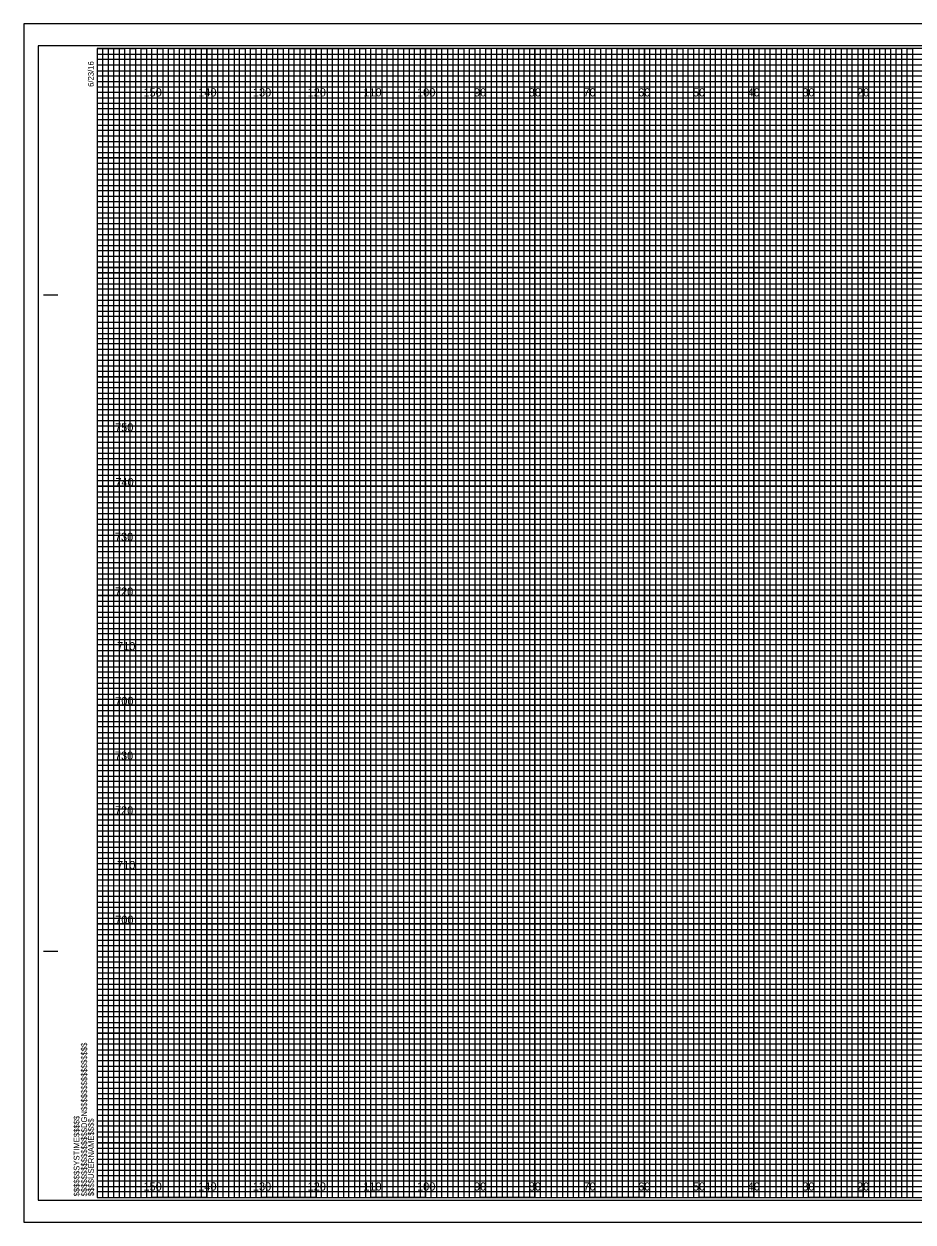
# Model space of a CAD drawing. Extents: x -397 to 323, y -4 to 654.
# Drawn here: x -13.4 to 149.1, y -4.5 to 214.5 of the extents above; entities that cross this region are included whole.
import ezdxf

# ---------------------------------------------------------------- set-up
doc = ezdxf.new("R2010")
doc.units = 0
for name, color, linetype in [('Default', 7, 'Continuous'), ('Prop XS Elevation Labels', 7, 'Continuous'), ('Prop XS Offset Labels', 7, 'Continuous'), ('Sheet Cross Section CELL', 7, 'Continuous'), ('Sheet Cross Section Grid Major CELL', 7, 'Continuous'), ('Sheet Cross Section Grid Middle CELL', 7, 'Continuous'), ('Sheet Cross Section Grid Minor 1 CELL', 7, 'Continuous'), ('Sheet Cross Section Grid Minor 2 CELL', 7, 'Continuous'), ('Sheet Cutting Line CELL', 7, 'Continuous'), ('Sheet DOT Grid CELL', 7, 'Continuous'), ('Sheet Plot Border Inside CELL', 7, 'Continuous'), ('Sheet Plot Border Outside CELL', 7, 'Continuous')]:
    doc.layers.add(name, color=color, linetype=linetype)

msp = doc.modelspace()

# ---------------------------------------------------------------- linework, layer by layer
at = {"layer": 'Default'}
msp.add_lwpolyline([(-13.4, -4.5), (323.3, -4.5), (323.3, 214.5), (-13.4, 214.5)], close=True, dxfattribs=at)
at = {"layer": 'Sheet Cross Section CELL'}
for p, q in [((-9.8, 165), (-7.3, 165)), ((-9.7, 165), (-7.2, 165)), ((-9.8, 45), (-7.3, 45)), ((-9.7, 45), (-7.2, 45)), ((0, 0), (0, 0)), ((0, 0), (0, 0)), ((0, 0), (0, 0)), ((0, 0), (0, 0)), ((0, 0), (0, 0)), ((0, 0), (0, 0)), ((0, 0), (0, 0))]:
    msp.add_line(p, q, dxfattribs=at)
msp.add_lwpolyline([(320, 210), (0, 210), (0, 0), (320, 0)], close=True, dxfattribs=at)
at = {"layer": 'Sheet Cross Section Grid Major CELL'}
for p, q in [((10, 210), (0, 210)), ((10, 0), (10, 210)), ((30, 210), (20, 210)), ((20, 210), (20, 0)), ((30, 0), (30, 210)), ((50, 210), (40, 210)), ((40, 210), (40, 0)), ((50, 0), (50, 210)), ((70, 210), (60, 210)), ((60, 210), (60, 0)), ((70, 0), (70, 210)), ((90, 210), (80, 210)), ((80, 210), (80, 0)), ((90, 0), (90, 210)), ((110, 210), (100, 210)), ((100, 210), (100, 0)), ((110, 0), (110, 210)), ((130, 210), (120, 210)), ((120, 210), (120, 0)), ((130, 0), (130, 210)), ((150, 210), (140, 210)), ((140, 210), (140, 0)), ((20, 0), (10, 0)), ((40, 0), (30, 0)), ((60, 0), (50, 0)), ((80, 0), (70, 0)), ((100, 0), (90, 0)), ((120, 0), (110, 0)), ((140, 0), (130, 0))]:
    msp.add_line(p, q, dxfattribs=at)
for points in [[(0, 200), (320, 200), (320, 190), (0, 190)], [(0, 180), (320, 180), (320, 170), (0, 170)], [(0, 160), (320, 160), (320, 150), (0, 150)], [(0, 140), (320, 140), (320, 130), (0, 130)], [(0, 120), (320, 120), (320, 110), (0, 110)], [(0, 100), (320, 100), (320, 90), (0, 90)], [(0, 80), (320, 80), (320, 70), (0, 70)], [(0, 60), (320, 60), (320, 50), (0, 50)], [(0, 40), (320, 40), (320, 30), (0, 30)], [(0, 20), (320, 20), (320, 10), (0, 10)]]:
    msp.add_lwpolyline(points, dxfattribs=at)
at = {"layer": 'Sheet Cross Section Grid Middle CELL'}
for points in [[(0, 210), (5, 210), (5, 0), (15, 0), (15, 210), (25, 210), (25, 0), (35, 0), (35, 210), (45, 210), (45, 0), (55, 0), (55, 210), (65, 210), (65, 0), (75, 0), (75, 210), (85, 210), (85, 0), (95, 0), (95, 210), (105, 210), (105, 0), (115, 0), (115, 210), (125, 210), (125, 0), (135, 0), (135, 210), (145, 210), (145, 0), (155, 0)], [(0, 205), (275, 205)], [(0, 185), (320, 185), (320, 195), (0, 195)], [(0, 165), (320, 165), (320, 175), (0, 175)], [(0, 145), (320, 145), (320, 155), (0, 155)], [(0, 125), (320, 125), (320, 135), (0, 135)], [(0, 105), (320, 105), (320, 115), (0, 115)], [(0, 85), (320, 85), (320, 95), (0, 95)], [(0, 65), (320, 65), (320, 75), (0, 75)], [(0, 45), (320, 45), (320, 55), (0, 55)], [(0, 25), (320, 25), (320, 35), (0, 35)], [(0, 5), (320, 5), (320, 15), (0, 15)]]:
    msp.add_lwpolyline(points, dxfattribs=at)
at = {"layer": 'Sheet Cross Section Grid Minor 1 CELL'}
for p, q in [((0, 209), (260, 209)), ((260, 207.98), (0, 207.98)), ((0, 207.98), (0, 207)), ((0, 207), (260, 207)), ((260, 205.89), (0, 205.89)), ((0, 205.89), (0, 204)), ((0, 204), (320, 204))]:
    msp.add_line(p, q, dxfattribs=at)
for points in [[(0, 203), (270, 203), (320, 203), (320, 202), (0, 202)], [(0, 201), (320, 201), (320, 199), (0, 199)], [(0, 198), (320, 198), (320, 197), (0, 196.98)], [(0, 196), (320, 196), (320, 194), (0, 194)], [(0, 193), (320, 193), (320, 192), (0, 192)], [(0, 191), (320, 191), (320, 189), (0, 189)], [(0, 188), (320, 188), (320, 187), (0, 187)], [(0, 186), (320, 186), (320, 184), (0, 184)], [(0, 183), (320, 183), (320, 182), (0, 182)], [(0, 181), (320, 181), (320, 179), (0, 179)], [(0, 178), (320, 178), (320, 177), (0, 177)], [(0, 176), (320, 176), (320, 173.95), (320, 173), (320, 172), (0, 172)], [(0, 174), (320, 174), (320, 173), (0, 173)], [(0, 171), (320, 171), (320, 169), (0, 169.03)], [(0, 169.03), (320, 169), (320, 168), (0, 168)], [(0, 167), (320, 167), (320, 166), (0, 166)], [(0, 164), (320, 164), (320, 163), (0, 163)], [(0, 162), (320, 162), (320, 161), (0, 161)], [(-0.07, 158.89), (320, 158.89), (320, 157.88), (-0.07, 157.88)], [(0, 157), (320, 157), (320, 156), (0, 156)], [(0, 154), (320, 154), (320, 153), (0, 153)], [(0, 152), (320, 152), (320, 151), (0, 151)], [(0, 149), (320, 149), (320, 148), (0, 148)], [(0, 147), (320, 147), (320, 146), (0, 146)], [(0, 144), (320, 144), (320, 143), (0, 143)], [(0, 142), (320, 142), (320, 141), (0, 141)], [(0, 139), (320, 139), (319.99, 137.98), (0, 138)], [(0, 137), (320, 137), (320, 136), (0, 136)], [(0, 134), (320, 134), (320, 133), (0, 133)], [(0, 132), (320, 132), (320, 131), (0, 131)], [(0, 129), (320, 129), (320, 128), (0, 128)], [(0, 127), (320, 127), (320, 126), (0, 126)], [(0, 124), (320, 124), (320, 123), (0, 123)], [(0, 122), (320, 122), (320, 121), (0, 121)], [(0, 119), (320, 119), (320, 118), (0, 118)], [(0, 116.99), (320.07, 116.91), (320, 116), (0, 116)], [(0, 114), (320, 114), (320, 113), (0, 113)], [(0, 112), (320, 112), (320, 111), (0, 111)], [(0, 109), (320, 109), (320, 108), (0, 108)], [(0, 107), (320, 107), (320, 106), (0, 106)], [(0, 104), (320, 104), (320, 103), (0, 103)], [(0, 102), (320, 102), (320, 101), (0, 101)], [(0, 99), (320, 99), (320, 98), (0, 98)], [(0, 97), (320, 97), (320, 96), (0, 96)], [(0, 94), (320, 94), (320, 93), (0, 93)], [(0, 92), (320, 92), (320, 91), (0, 91)], [(0, 89), (320, 89), (320, 88), (0, 88)], [(0, 87), (320, 87), (320, 86), (0, 86)], [(0, 84), (320, 84), (320, 83), (0, 83)], [(0, 82), (320, 82), (320, 81), (0, 81)], [(0, 79), (320, 79), (319.99, 77.98), (0, 78)], [(0, 77), (320, 77), (320, 76), (0, 76)], [(0, 74), (320, 74), (320, 73), (0, 73)], [(0, 72), (320, 72), (320, 71), (0, 71)], [(0, 69), (320, 69), (320, 68), (0, 68)], [(0, 67), (320, 67), (320, 66), (0, 66)], [(0, 64), (320, 64), (320, 63), (0, 63)], [(0, 62), (320, 62), (320, 61), (0, 61)], [(0, 59), (320, 59), (320, 58), (0, 58)], [(0, 56.99), (320.07, 56.91), (320, 56), (0, 56)], [(0, 54), (320, 54), (320, 53), (0, 53)], [(0, 52), (320, 52), (320, 51), (0, 51)], [(0, 49), (320, 49), (320, 48), (0, 48)], [(0, 47), (320, 47), (320, 46), (0, 46)], [(0, 44), (320, 44), (320, 43), (0, 43)], [(0, 42), (320, 42), (320, 41), (0, 41)], [(0, 39), (320, 39), (320, 38), (0, 38)], [(0, 37), (320, 37), (320, 36), (0, 36)], [(0, 34), (320, 34), (320, 33), (0, 33)], [(0, 32), (320, 32), (320, 31), (0, 31)], [(0, 29), (320, 29), (320, 28), (0, 28)], [(0, 27), (320, 27), (320, 26), (0, 26)], [(0, 24), (320, 24), (320, 23), (0, 23)], [(0, 22), (320, 22), (320, 21), (0, 21)], [(0, 19), (320, 19), (320, 18), (0, 18)], [(0, 17), (320, 17), (320, 16), (0, 16)], [(0, 14), (320, 14), (320, 13), (0, 13)], [(0, 12), (320, 12), (320, 11), (0, 11)], [(0, 9), (320, 9), (320, 8), (0, 8)], [(0, 7), (320, 7), (320, 6), (0, 6)], [(0, 4), (320, 4), (320, 3), (0, 3)], [(0, 2), (320, 2), (320, 1), (0, 1)]]:
    msp.add_lwpolyline(points, dxfattribs=at)
at = {"layer": 'Sheet Cross Section Grid Minor 2 CELL'}
for points in [[(0, 0), (1, 0), (1, 210), (2, 210), (2, 0)], [(2, 0), (3, 0), (3, 210), (4, 210), (4, 0)], [(5, 0), (6, 0), (6, 210), (7, 210), (7, 0)], [(7, 0), (8, 0), (8, 210), (9, 210), (9, 0)], [(10, 0), (11, 0), (11, 210), (12, 210), (12, 0)], [(12, 0), (13, 0), (13, 210), (14, 210), (14, 0)], [(15, 0), (16, 0), (16, 210), (17, 210), (17, 0)], [(17, 0), (18, 0), (18, 210), (19, 210), (19, 0)], [(20, 0), (21, 0), (21, 210), (22, 210), (22, 0)], [(22, 0), (23, 0), (23, 210), (24, 210), (24, 0)], [(25, 0), (26, 0), (26, 210), (27, 210), (27, 0)], [(27, 0), (28, 0), (28, 210), (29, 210), (29, 0)], [(30, 0), (31, 0), (31, 210), (32, 210), (32, 0)], [(32, 0), (33, 0), (33, 210), (34, 210), (34, 0)], [(35, 0), (36, 0), (36, 210), (37, 210), (37, 0)], [(37, 0), (38, 0), (38, 210), (39, 210), (39, 0)], [(40, 0), (41, 0), (41, 210), (42, 210), (42, 0)], [(42, 0), (43, 0), (43, 210), (44, 210), (44, 0)], [(45, 0), (46, 0), (46, 210), (47, 210), (47, 0)], [(47, 0), (48, 0), (48, 210), (49, 210), (49, 0)], [(50, 0), (51, 0), (51, 210), (52, 210), (52, 0)], [(52, 0), (53, 0), (53, 210), (54, 210), (54, 0)], [(55, 0), (56, 0), (56, 210), (57, 210), (57, 0)], [(57, 0), (58, 0), (58, 210), (59, 210), (59, 0)], [(60, 0), (61, 0), (61, 210), (62, 210), (62, 0)], [(62, 0), (63, 0), (63, 210), (64, 210), (64, 0)], [(65, 0), (66, 0), (66, 210), (67, 210), (67, 0)], [(67, 0), (68, 0), (68, 210), (69, 210), (69, 0)], [(70, 0), (71, 0), (71, 210), (72, 210), (72, 0)], [(72, 0), (73, 0), (73, 210), (74, 210), (74, 0)], [(75, 0), (76, 0), (76, 210), (77, 210), (77, 0)], [(77, 0), (78, 0), (78, 210), (79, 210), (79, 0)], [(80, 0), (81, 0), (81, 210), (82, 210), (82, 0)], [(82, 0), (83, 0), (83, 210), (84, 210), (84, 0)], [(85, 0), (86, 0), (86, 210), (87, 210), (87, 0)], [(87, 0), (88, 0), (88, 210), (89, 210), (89, 0)], [(90, 0), (91, 0), (91, 210), (92, 210), (92, 0)], [(92, 0), (93, 0), (93, 210), (94, 210), (94, 0)], [(95, 0), (96, 0), (96, 210), (97, 210), (97, 0)], [(97, 0), (98, 0), (98, 210), (99, 210), (99, 0)], [(100, 0), (101, 0), (101, 210), (102, 210), (102, 0)], [(102, 0), (103, 0), (103, 210), (104, 210), (104, 0)], [(105, 0), (106, 0), (106, 210), (107, 210), (107, 0)], [(107, 0), (108, 0), (108, 210), (109, 210), (109, 0)], [(110, 0), (111, 0), (111, 210), (112, 210), (112, 0)], [(112, 0), (113, 0), (113, 210), (114, 210), (114, 0)], [(115, 0), (116, 0), (116, 210), (117, 210), (117, 0)], [(117, 0), (118, 0), (118, 210), (119, 210), (119, 0)], [(120, 0), (121, 0), (121, 210), (122, 210), (122, 0)], [(122, 0), (123, 0), (123, 210), (124, 210), (124, 0)], [(125, 0), (126, 0), (126, 210), (127, 210), (127, 0)], [(127, 0), (128, 0), (128, 210), (129, 210), (129, 0)], [(130, 0), (131, 0), (131, 210), (132, 210), (132, 0)], [(132, 0), (133, 0), (133, 210), (134, 210), (134, 0)], [(135, 0), (136, 0), (136, 210), (137, 210), (137, 0)], [(137, 0), (138, 0), (138, 210), (139, 210), (139, 0)], [(140, 0), (141, 0), (141, 210), (142, 210), (142, 0)], [(142, 0), (143, 0), (143, 210), (144, 210), (144, 0)], [(145, 0), (146, 0), (146, 210), (147, 210), (147, 0)], [(147, 0), (148, 0), (148, 210), (149, 210), (149, 0)]]:
    msp.add_lwpolyline(points, dxfattribs=at)
at = {"layer": 'Sheet Cutting Line CELL'}
for p, q in [((323.3, 214.5), (-13.4, 214.5)), ((-13.4, 214.5), (-13.4, -4.5)), ((-13.4, -4.5), (323.3, -4.5))]:
    msp.add_line(p, q, dxfattribs=at)
at = {"layer": 'Sheet DOT Grid CELL'}
for p, q in [((10, 0), (10, 210)), ((20, 0), (20, 210)), ((30, 0), (30, 210)), ((40, 0), (40, 210)), ((50, 0), (50, 210)), ((60, 0), (60, 210)), ((70, 0), (70, 210)), ((80, 0), (80, 210)), ((90, 0), (90, 210)), ((100, 0), (100, 210)), ((110, 0), (110, 210)), ((120, 0), (120, 210)), ((130, 0), (130, 210)), ((140, 0), (140, 210)), ((0, 200), (320, 200)), ((0, 190), (320, 190)), ((0, 180), (320, 180)), ((0, 170), (320, 170)), ((0, 160), (320, 160)), ((0, 150), (320, 150)), ((0, 140), (320, 140)), ((0, 130), (320, 130)), ((0, 120), (320, 120)), ((0, 110), (320, 110)), ((0, 100), (320, 100)), ((0, 90), (320, 90)), ((0, 80), (320, 80)), ((0, 70), (320, 70)), ((0, 60), (320, 60)), ((0, 50), (320, 50)), ((0, 40), (320, 40)), ((0, 30), (320, 30)), ((0, 20), (320, 20)), ((0, 10), (320, 10))]:
    msp.add_line(p, q, dxfattribs=at)
at = {"layer": 'Sheet Plot Border Inside CELL'}
msp.add_lwpolyline([(-10.8, -0.5), (322.4, -0.5), (322.4, 210.5), (-10.8, 210.5)], close=True, dxfattribs=at)
at = {"layer": 'Sheet Plot Border Outside CELL'}
msp.add_lwpolyline([(-13.4, -4.5), (323.3, -4.5), (323.3, 214.5), (-13.4, 214.5)], close=True, dxfattribs=at)

# ---------------------------------------------------------------- texts
at = {"layer": 'Prop XS Elevation Labels'}
for s, p in [('750', (3.25, 140)), ('740', (3.3, 130)), ('730', (3.22, 120)), ('720', (3.23, 110)), ('710', (3.61, 100)), ('700', (3.28, 90)), ('730', (3.22, 80)), ('720', (3.23, 70)), ('710', (3.61, 60)), ('700', (3.28, 50))]:
    msp.add_text(s, height=1.5, dxfattribs=at).set_placement(p)
at = {"layer": 'Prop XS Offset Labels'}
for s, p in [('150', (8.44, 201.25)), ('140', (18.44, 201.25)), ('130', (28.44, 201.25)), ('120', (38.44, 201.25)), ('110', (48.62, 201.25)), ('100', (58.44, 201.25)), ('90', (68.86, 201.25)), ('80', (78.86, 201.25)), ('70', (88.86, 201.25)), ('60', (98.86, 201.25)), ('50', (108.86, 201.25)), ('40', (118.86, 201.25)), ('30', (128.86, 201.25)), ('20', (138.86, 201.25)), ('150', (8.44, 1.25)), ('140', (18.44, 1.25)), ('130', (28.44, 1.25)), ('120', (38.44, 1.25)), ('110', (48.62, 1.25)), ('100', (58.44, 1.25)), ('90', (68.86, 1.25)), ('80', (78.86, 1.25)), ('70', (88.86, 1.25)), ('60', (98.86, 1.25)), ('50', (108.86, 1.25)), ('40', (118.86, 1.25)), ('30', (128.86, 1.25)), ('20', (138.86, 1.25))]:
    msp.add_text(s, height=1.5, dxfattribs=at).set_placement(p)
at = {"layer": 'Sheet Cross Section CELL'}
for s, p in [('6/23/16', (-0.65, 203)), ('$$$$$$$$$$$$$$$$DGN$$$$$$$$$$$$$$$$', (-1.88, 0.18)), ('$$$$$$SYSTIME$$$$$', (-3.26, 0.18)), ('$$$$USERNAME$$$$', (-0.62, 0.23))]:
    msp.add_text(s, height=1.05, rotation=90, dxfattribs=at).set_placement(p)

doc.saveas('drawing.dxf')
